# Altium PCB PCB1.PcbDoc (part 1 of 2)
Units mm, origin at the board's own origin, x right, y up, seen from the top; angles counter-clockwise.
Board outline 130 x 90 mm, 2 copper layers (Top Layer, Bottom Layer), stack 1.671 mm thick; 127 components, 100 nets, 530 pads, 140 vias.
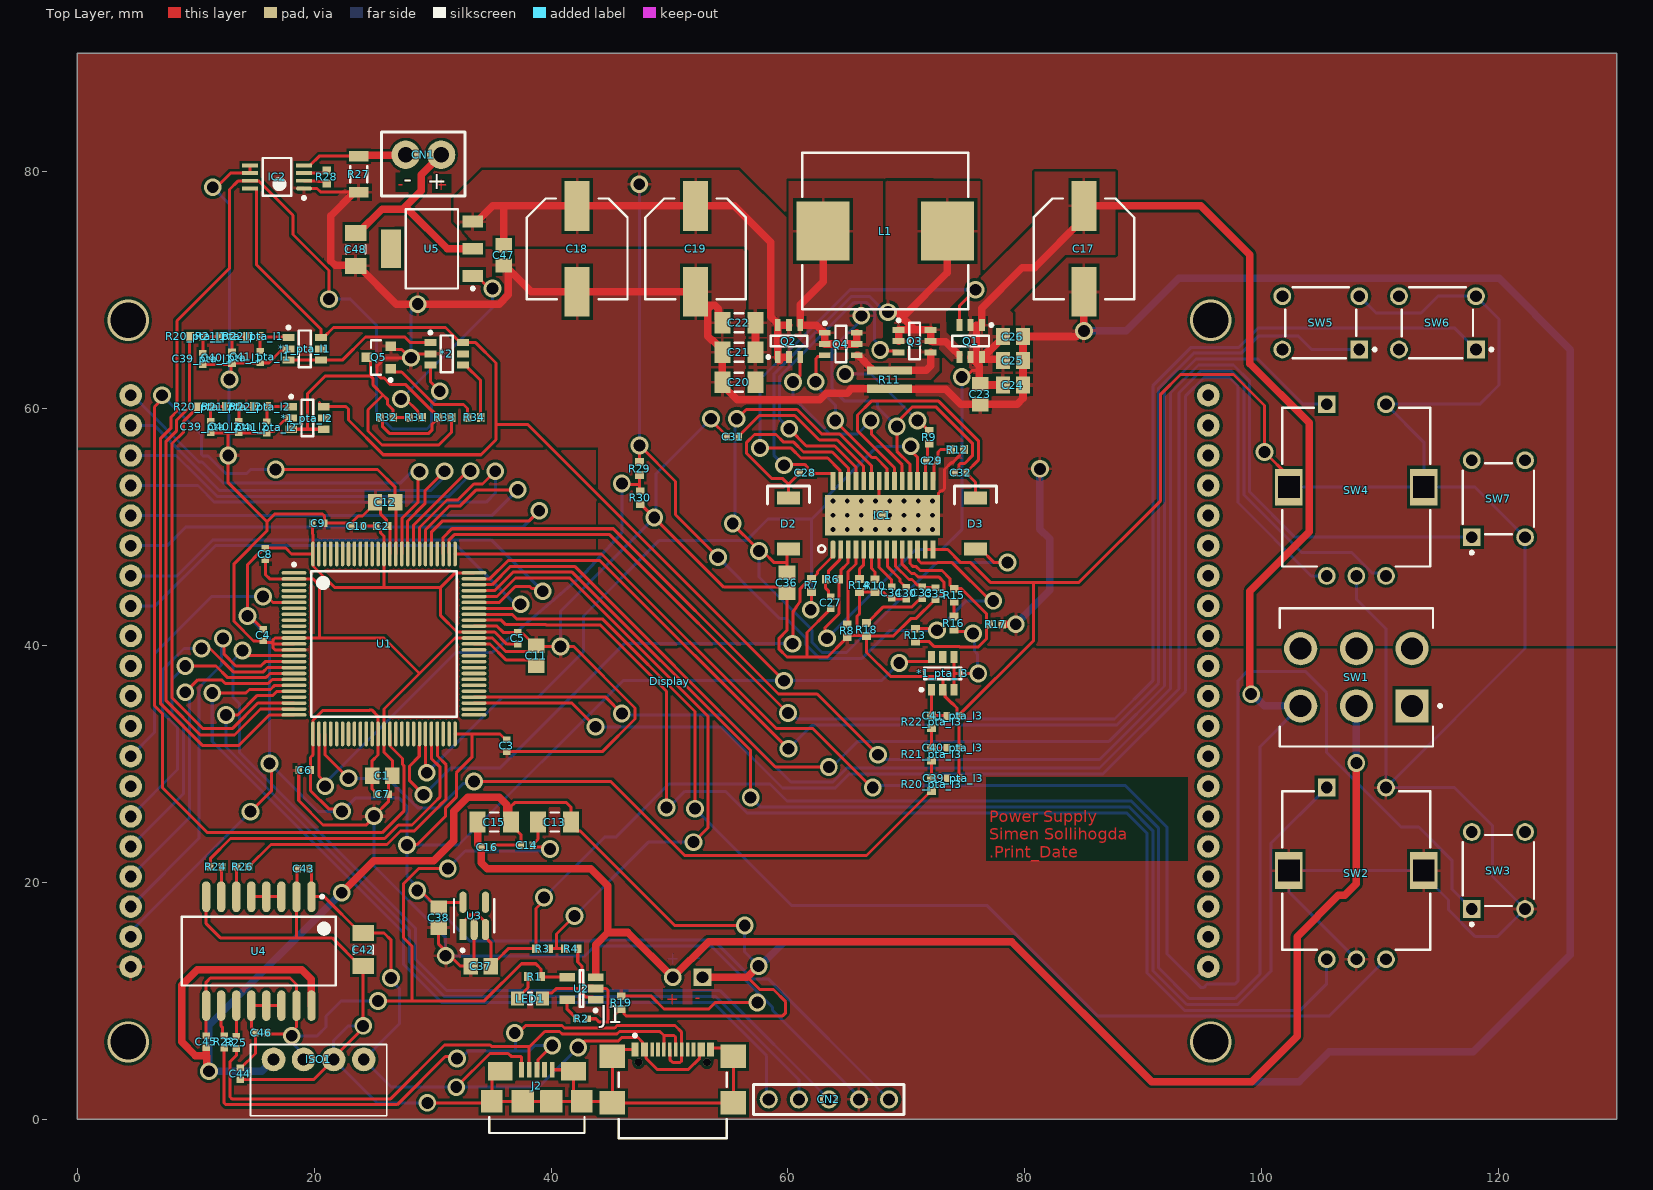
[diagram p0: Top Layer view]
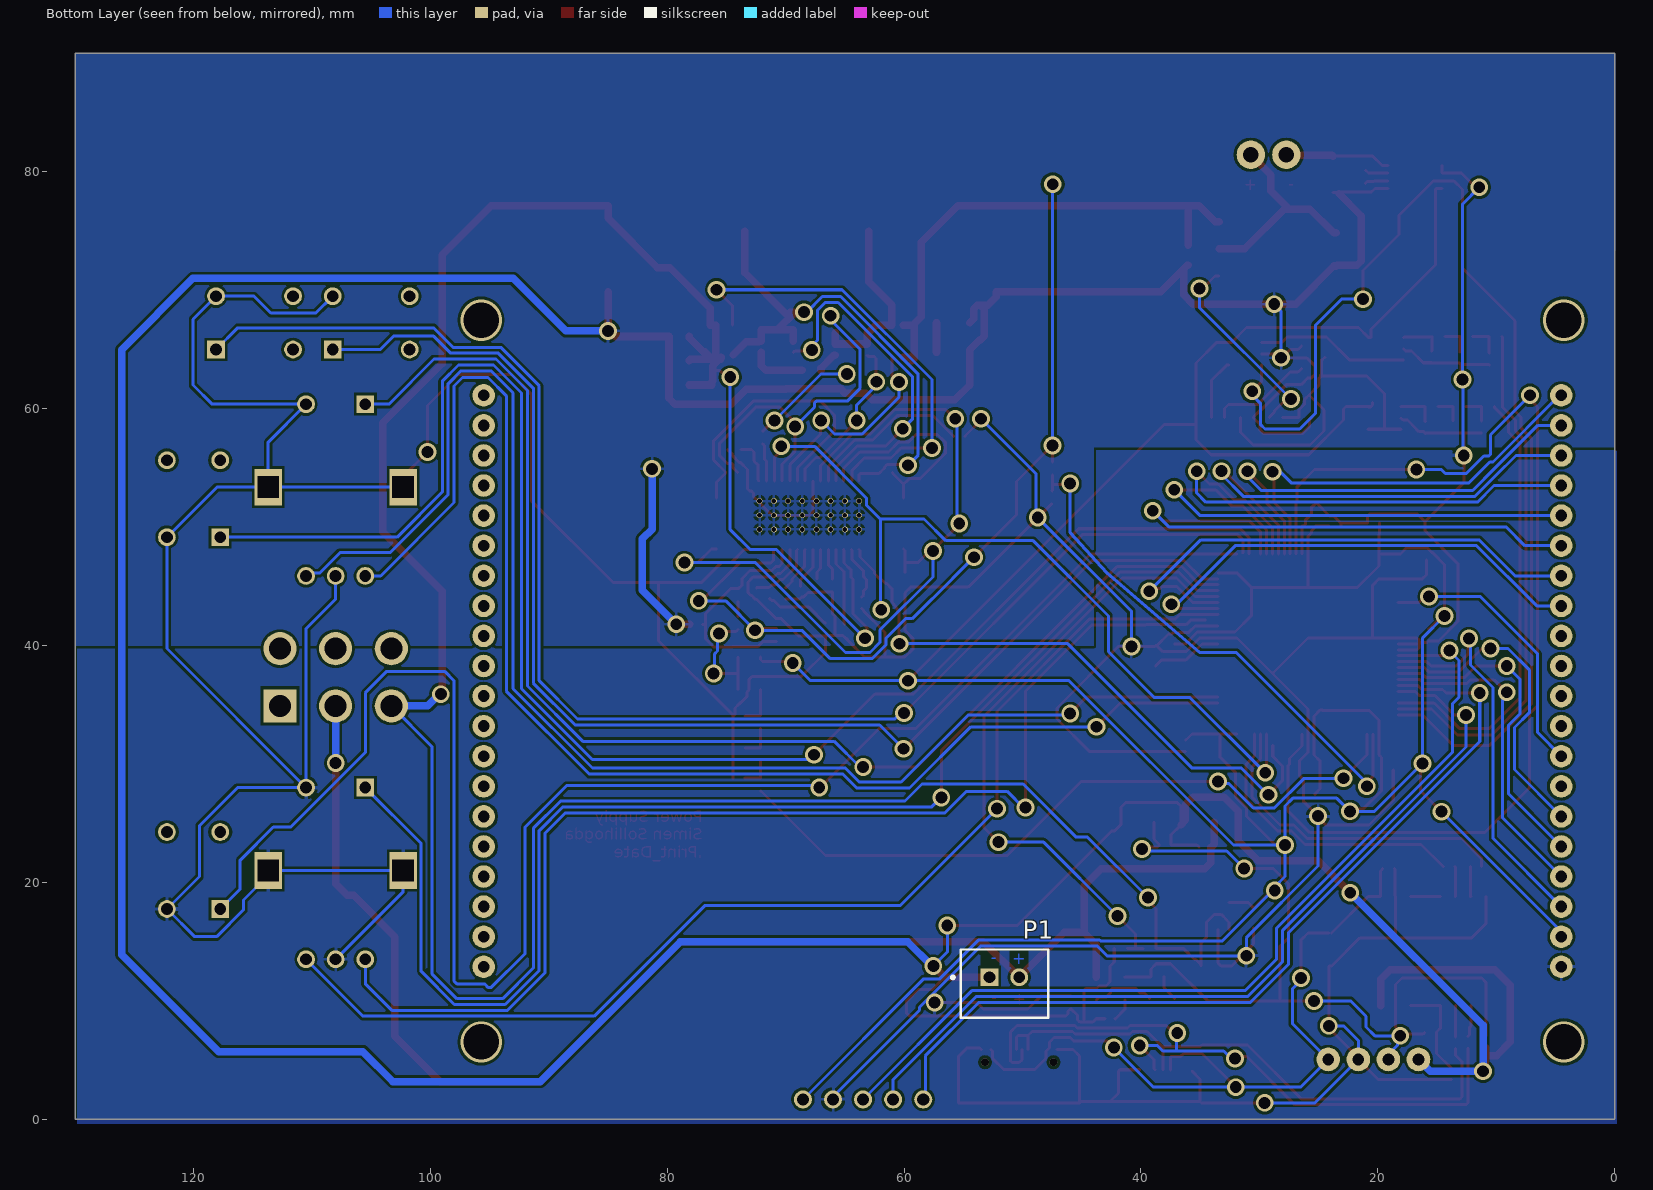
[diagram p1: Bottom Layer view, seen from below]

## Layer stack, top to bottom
Top Solder: solder mask 0.0102, Solder Resist, Dk 3.5
Top Layer: signal copper 0.0356
Dielectric 1: dielectric 1.6, FR-4, Dk 4.8
Bottom Layer: signal copper 0.0356
Bottom Solder: solder mask 0.0102, Solder Resist, Dk 3.5

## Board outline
0,0 130,0 130,90 0,90

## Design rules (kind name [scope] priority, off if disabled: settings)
Clearance Clearance_2 [InComponent('u1') or InComponent('J1') vs IsWire] p1: gap=0.152 ignorepadtopadclearanceinfootprint=FALSE
Clearance Clearance_1 [IsPad vs IsPad] p2: gap=0.152 ignorepadtopadclearanceinfootprint=FALSE
Clearance [All] p3: gap=0.241 ignorepadtopadclearanceinfootprint=FALSE
HoleSize HoleSize_1 [InComponent('IC1') or InComponent('J1')] p1: absolutevalues=TRUE maxlimit=2.54 minlimit=0.3 maxpercent=80.000 minpercent=20.000
HoleSize [All] p2: absolutevalues=TRUE maxlimit=60 minlimit=0.8 maxpercent=80.000 minpercent=20.000
MinimumSolderMaskSliver [All] p1: minsoldermaskwidth=0.102
PolygonConnect [All] p1: connectstyle=Relief reliefconductorwidth=0.254 reliefentries=4 polygonreliefangle="90 Angle" airgapwidth=0.254
RoutingVias [All] p1: holewidth=0.4 width=0.56 viastyle="Through Hole" minholewidth=0.4 minwidth=0.56 maxholewidth=1 maxwidth=2
SilkToSilkClearance [All] p1 off: silktosilkclearance=0.254
SilkToSolderMaskClearance [IsPad] p1: minsilkscreentomaskgap=0 clearancetoexposedcopper=FALSE
SolderMaskExpansion [All] p1: expansion=0.102 istentingtop=FALSE
Width [All] p1: maxlimit=2.54 minlimit=0.203 preferedwidth=0.254
26 further rules are at their usual default settings.

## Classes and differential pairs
component class U_programmer: CN2
component class U_linear_regulator: *2 C47 C48 Q5 R31 R32 R33 R34 U5
component class U_Display: Display
component class pta_I1: *1_pta_I1 C39_pta_I1 C40_pta_I1 C41_pta_I1 R20_pta_I1 R21_pta_I1 R22_pta_I1
component class U_Driver: CN1 R29 R30
component class U_mcu: C1 C2 C3 C4 C5 C6 C7 C8 C9 C10 C11 C12 U1
component class U_knobs: SW2 SW3 SW4 SW5 SW6 SW7
component class U_current_sense: IC2 R27 R28
component class U_Booster: C17 C18 C19 C20 C21 C22 C23 C24 C25 C26 C27 C28 C29 C30 C31 C32 C33 C34 C35 C36 D2 D3 IC1 L1 Q1 Q2 Q3 Q4 R6 R7 R8 R8_U_Booster R9 R10 R11 R12 R13 R14 R15 R16 R17 R18
component class pta_I3: *1_pta_I3 C39_pta_I3 C40_pta_I3 C41_pta_I3 R20_pta_I3 R21_pta_I3 R22_pta_I3
component class pta_I2: *1_pta_I2 C39_pta_I2 C40_pta_I2 C41_pta_I2 R20_pta_I2 R21_pta_I2 R22_pta_I2
component class U_usb_isolator: C42 C43 C44 C45 C46 ISO1 R23 R24 R25 R26 U4
component class U_usb: J1 J2
component class LDO: C37 C38 R19 U3
channel class pwm_to_analog: pta_I3 pta_V
component class Battery: C13 C14 C15 C16 LED1 P1 R1 R2 R3 R4 SW1 U2

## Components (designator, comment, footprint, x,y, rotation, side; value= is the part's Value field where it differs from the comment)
*1_pta_I1 "LMV341IDBVR" SOT95P280X145-6N 19.189,65.05 r0 top (schematic designator *1)
*1_pta_I2 "LMV341IDBVR" SOT95P280X145-6N 19.425,59.214 r0 top (schematic designator *1)
*1_pta_I3 "LMV341IDBVR" SOT95P280X145-6N 73.075,37.641 r90 top (schematic designator *1)
*2 "LMV341IDBVR" SOT95P280X145-6N 31.179,64.625 r0 top
C1 "CL21B105KBFNNNG" CAP0805 25.739,29 r180 top
C2 "GRM155R71H104ME14D" cap0402 25.739,50.092 r180 top value=100nF
C3 "GRM155R71H104ME14D" cap0402 36.243,31.53 r90 top value=100nF
C4 "GRM155R71H104ME14D" cap0402 15.704,40.886 r90 top value=100nF
C5 "GRM155R71H104ME14D" cap0402 37.176,40.617 r270 top value=100nF
C6 "GRM155R71H104ME14D" cap0402 19.189,29.487 r0 top value=100nF
C7 "GRM155R71H104ME14D" cap0402 25.783,27.436 r180 top value=100nF
C8 "GRM155R71H104ME14D" cap0402 15.867,47.728 r90 top value=100nF
C9 "GRM155R71H104ME14D" cap0402 20.349,50.342 r180 top value=100nF
C10 "GRM155R71H104ME14D" cap0402 23.622,50.092 r0 top value=100nF
C11 "CL21B105KBFNNNG" CAP0805 38.752,39.136 r270 top
C12 "CL21B105KBFNNNG" CAP0805 25.986,52.108 r0 top
C13 "CL31A106MBHNNNE" Chip2PinSM127P600-8N#1 40.3,25.095 r180 top
C14 "GRM155R71H104ME14D" cap0402 37.95,23.145 r0 top value=100nF
C15 "CL31A106MBHNNNE" Chip2PinSM127P600-8N#1 35.2,25.095 r180 top
C16 "GRM155R71H104ME14D" cap0402 34.6,22.97 r180 top value=100nF
C17 "EEE-1HA101UP" CAPAE9983X102N 84.999,73.5 r270 top
C18 "EEE-1HA101UP" CAPAE9983X102N 42.199,73.5 r270 top
C19 "EEE-1HA101UP" CAPAE9983X102N 52.199,73.5 r270 top
C20 "CL31A106MBHNNNE" Chip2PinSM127P600-8N#1 55.86,62.225 r0 top
C21 "CL31A106MBHNNNE" Chip2PinSM127P600-8N#1 55.86,64.762 r0 top
C22 "CL31A106MBHNNNE" Chip2PinSM127P600-8N#1 55.86,67.25 r0 top
C23 "CL21B105KBFNNNG" CAP0805 76.25,61.226 r90 top
C24 "CL21B105KBFNNNG" CAP0805 79,62 r180 top
C25 "CL21B105KBFNNNG" CAP0805 79,64.069 r180 top
C26 "CL21B105KBFNNNG" CAP0805 79,66.096 r180 top
C27 "GRM155R71H104ME14D" cap0402 63.6,43.606 r270 top value=100nF
C28 "GRM155R71H104ME14D" cap0402 61.482,54.6 r180 top value=100nF
C29 "885012005078" cap0402 72.163,55.623 r0 top
C30 "GRM155R71H104ME14D" cap0402 69.993,44.42 r90 top value=100nF
C31 "GRM155R71H104ME14D" cap0402 55.345,57.646 r0 top value=100nF
C32 "GRM155R71H104ME14D" cap0402 74.578,54.6 r0 top value=100nF
C33 "CC0402KRX7R9BB223" cap0402 71.343,44.45 r90 top
C34 "885012005080" cap0402 68.763,44.475 r90 top
C35 "885012005080" cap0402 72.463,44.376 r90 top
C36 "CL21B105KBFNNNG" CAP0805 59.917,45.3 r270 top
C37 "CL21B105KBFNNNG" CAP0805 34.055,12.921 r0 top
C38 "CL21B105KBFNNNG" CAP0805 30.5,17.015 r90 top
C39_pta_I1 "GRM155R71H104ME14D" cap0402 10.575,64.2 r90 top value=100nF (schematic designator C39)
C39_pta_I2 "GRM155R71H104ME14D" cap0402 11.249,58.463 r90 top value=100nF (schematic designator C39)
C39_pta_I3 "GRM155R71H104ME14D" cap0402 73.951,28.791 r180 top value=100nF (schematic designator C39)
C40_pta_I1 "GRM155R71H104ME14D" cap0402 13.05,64.3 r90 top value=100nF (schematic designator C40)
C40_pta_I2 "GRM155R71H104ME14D" cap0402 13.625,58.463 r90 top value=100nF (schematic designator C40)
C40_pta_I3 "GRM155R71H104ME14D" cap0402 73.925,31.366 r180 top value=100nF (schematic designator C40)
C41_pta_I1 "GRM155R71H104ME14D" cap0402 15.454,64.375 r90 top value=100nF (schematic designator C41)
C41_pta_I2 "GRM155R71H104ME14D" cap0402 15.979,58.416 r90 top value=100nF (schematic designator C41)
C41_pta_I3 "GRM155R71H104ME14D" cap0402 73.925,34.05 r180 top value=100nF (schematic designator C41)
C42 "CL31A106MBHNNNE" Chip2PinSM127P600-8N#1 24.127,14.321 r90 top
C43 "GRM155R71H104ME14D" cap0402 19.095,21.164 r0 top value=100nF
C44 "GRM155R71H104ME14D" cap0402 13.762,3.833 r270 top value=100nF
C45 "GRM155R71H104ME14D" cap0402 10.872,6.545 r90 top value=100nF
C46 "GRM155R71H104ME14D" cap0402 15.532,7.311 r0 top value=100nF
C47 "CL21B105KBFNNNG" CAP0805 36,72.95 r90 top
C48 "CL31A106MBHNNNE" Chip2PinSM127P600-8N#1 23.495,73.45 r90 top
CN1 "BU-P6883" 6883-Footprint-1 29.213,81.447 r180 top
CN2 "PPTC041LFBN-RC" PR20203VBNN-Footprint-1 63.46,1.665 r90 top locked
D2 "PMEG60T10ELPX" SODFL470X110-2N 60.048,50.3 r270 top
D3 "PMEG60T10ELPX" SODFL470X110-2N 75.841,50.3 r270 top
Display "2050" 2050-Footprint-1 50,37 r90 top locked
IC1 "LM5175-Q1" HTSSOP-28 68,51 r90 top
IC2 "AD8236" 8-MSOP 16.852,79.572 r180 top
ISO1 "RFM-0505S" RFM-0505S-Footprint-1 20.369,5.045 r180 top locked
J1 "USB4110-GF-A" FP-USB4110-GF-A-MFG 50.275,2.204 r0 top locked
J2 "10118192-0001LF" FCI-10118192-0001LF-5_V 38.8,1.5 r0 top locked
L1 "7443551730" INDP130128X65N 68.219,75 r180 top
LED1 "150080BS75000" 0805_A 38.227,10.181 r180 top
P1 "B2B-XH-A(LF)(SN)" JST-B2B-XH-A_V 51.525,11.981 r180 bottom
Q1 "PMN55ENEX" TSOP95P280X110-6N_PMN55ENE 75.425,65.712 r270 top
Q2 "PMN55ENEX" TSOP95P280X110-6N_PMN55ENE 60.087,65.712 r90 top
Q3 "PMN55ENEX" TSOP95P280X110-6N_PMN55ENE 70.697,65.712 r0 top
Q4 "PMN55ENEX" TSOP95P280X110-6N_PMN55ENE 64.465,65.462 r0 top
Q5 "MMBTA42LT1G" ONSC-SOT-23-3-318-08_V 25.445,64.325 r180 top
R1 "RC0402FR-071KL" SMD_0402(1005)_M 38.602,12.035 r0 top value=1k
R2 "RC0402FR-072K2L" RESC1005X40X25NL05T10 42.6,8.481 r180 top value=2.2k
R3 "RC0402FR-0710KL" SMD_0402(1005)_M 39.277,14.396 r180 top value=10k
R4 "RC0402FR-0710KL" SMD_0402(1005)_M 41.7,14.396 r180 top value=10k
R6 "RC0402FR-0710RL" SMD_0402(1005)_M 63.76,45.6 r0 top value=10
R7 "RC0402FR-0710KL" SMD_0402(1005)_M 62,45.075 r90 top value=10k
R8 "RC0402FR-0749K9L" SMD_0402(1005)_M 65.013,41.238 r90 top value=49.9k
R9 "RC0402FR-07100RL" SMD_0402(1005)_M 71.933,57.582 r90 top value=100
R10 "RC0402FR-07100KL" SMD_0402(1005)_M 67.36,45.05 r90 top value=100k
R11 "CFG0612-FX-R010ELF" Chip2PinSM127P600-8N#2 68.597,62.451 r90 top
R12 "RC0402FR-07100RL" SMD_0402(1005)_M 74.316,56.55 r0 top value=100
R13 "RC0402FR-07100k" SMD_0402(1005)_M 70.76,40.871 r90 top value=100k
R14 "RC0402FR-070RL" SMD_0402(1005)_M 66.056,45.075 r90 top value=0
R15 "RC0402FR-0710KL" SMD_0402(1005)_M 74.041,44.25 r270 top value=10k
R16 "RC0402FR-0710KL" SMD_0402(1005)_M 74.016,41.9 r270 top value=10k
R17 "CMP-008-0005-9" SMD_0402(1005)_M 77.55,41.792 r180 top value=10k
R18 "RC0402FR-0710KL" SMD_0402(1005)_M 66.638,41.35 r90 top value=10k
R19 "RC0402FR-070RL" SMD_0402(1005)_M 45.923,9.834 r90 top value=0
R20_pta_I1 "RC0402FR-0710KL" SMD_0402(1005)_M 10.05,66.1 r0 top value=10k (schematic designator R20)
R20_pta_I2 "RC0402FR-0710KL" SMD_0402(1005)_M 10.699,60.164 r0 top value=10k (schematic designator R20)
R20_pta_I3 "RC0402FR-0710KL" SMD_0402(1005)_M 72.125,28.266 r90 top value=10k (schematic designator R20)
R21_pta_I1 "RC0402FR-0710KL" SMD_0402(1005)_M 12.525,66.1 r0 top value=10k (schematic designator R21)
R21_pta_I2 "RC0402FR-0710KL" SMD_0402(1005)_M 13.075,60.177 r0 top value=10k (schematic designator R21)
R21_pta_I3 "RC0402FR-0710KL" SMD_0402(1005)_M 72.125,30.816 r90 top value=10k (schematic designator R21)
R22_pta_I1 "RC0402FR-0710KL" SMD_0402(1005)_M 14.854,66.1 r0 top value=10k (schematic designator R22)
R22_pta_I2 "RC0402FR-0710KL" SMD_0402(1005)_M 15.454,60.177 r0 top value=10k (schematic designator R22)
R22_pta_I3 "RC0402FR-0710KL" SMD_0402(1005)_M 72.125,33.561 r90 top value=10k (schematic designator R22)
R23 "RC0402FR-0724RL" RESC1005X40X25ML05T10 12.389,6.52 r90 top
R24 "RC0402FR-0724RL" RESC1005X40X25ML05T10 11.697,21.33 r180 top
R25 "RC0402FR-0724RL" RESC1005X40X25ML05T10 13.412,6.47 r90 top
R26 "RC0402FR-0724RL" RESC1005X40X25ML05T10 13.962,21.33 r0 top
R27 "ERJ-8BSFR10V" Chip2PinSM127P600-8N#3 23.758,79.797 r270 top value=0.1
R28 "RC0402FR-074K42L" SMD_0402(1005)_M 21.052,79.572 r270 top value=4.42k
R29 "CMP-008-0005-9" SMD_0402(1005)_M 47.474,54.943 r90 top value=10k
R30 "CMP-008-0005-9" SMD_0402(1005)_M 47.524,52.483 r90 top value=10k
R31 "RC0402FR-071KL" SMD_0402(1005)_M 28.575,59.264 r0 top value=1k
R32 "RC0402FR-071KL" SMD_0402(1005)_M 26.114,59.264 r0 top value=1k
R33 "RC0402FR-071KL" SMD_0402(1005)_M 31.036,59.264 r0 top value=1k
R34 "RC0402FR-071KL" SMD_0402(1005)_M 33.497,59.264 r0 top value=1k
SW1 "100DP1T2B3M2QEH" FP-100DP1T2B3M2QEH-MFG 108,37.317 r180 top
SW2 "PEC11R-4215F-S0024" BOUR-PEC11R-4XXXF-SXXXX_V 108,21 r0 top
SW3 "PTS645SM43SMTR92LFS" ITT-PTS645S-4_V 120,21 r90 top
SW4 "PEC11R-4215F-S0024" BOUR-PEC11R-4XXXF-SXXXX_V 108,53.376 r0 top
SW5 "PTS645SM43SMTR92LFS" ITT-PTS645S-4_V 105,67.25 r180 top
SW6 "PTS645SM43SMTR92LFS" ITT-PTS645S-4_V 114.85,67.25 r180 top
SW7 "PTS645SM43SMTR92LFS" ITT-PTS645S-4_V 120,52.394 r90 top
U1 "LMV341IDBVR" CYP-AX100_M 25.889,40.136 r0 top
U2 "MCP73832T-2ACI/OT" SOT-23-OT5_M 42.554,11.031 r180 top
U3 "TLV74333PDBVR" FP-DBV0005A-IPC_A 33.5,17.165 r90 top
U4 "ADUM4160BRIZ-RL" ADI-RI-16-1_M 15.317,14.19 r270 top
U5 "LT3080EST#TRPBF" LT-ST-3-SOT-223_M 29.936,73.5 r180 top

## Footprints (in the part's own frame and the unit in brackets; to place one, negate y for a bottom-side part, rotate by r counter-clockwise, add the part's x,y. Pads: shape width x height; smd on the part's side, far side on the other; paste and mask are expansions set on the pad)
8-MSOP [mm] "TSOP, 8-Leads, Body 3.00x3.00mm, Pitch 0.65mm, IPC Medium Density"
  oval 1.35x0.33 smd: 1(-2.275,0.975)
  rect 1.35x0.33 smd: 2(-2.275,0.325) 3(-2.275,-0.325) 4(-2.275,-0.975) 5(2.275,-0.975) 6(2.275,-0.325) 7(2.275,0.325) 8(2.275,0.975)
  silkscreen extent -2.4,-1.6 1.2,1.9, body extent -2.45,-1.6 2.45,1.6, height 0.95
0805_A [mm] "Chip LED, 2-Leads, Body 2.0x1.3mm, IPC Medium Density"
  rect 1.1x1.2 smd: 1(-1.05,0) 2(1.05,0)
  silkscreen extent -0.15,-0.5 0.15,0.5, body extent -1,-0.62 1,0.63, height 0.68
2050-Footprint-1 [mm]
  round 1.905 hole 1: 1(24.13,-45.5) 2(21.59,-45.5) 3(19.05,-45.5) 4(16.51,-45.5) 5(13.97,-45.5) 6(11.43,-45.5) 7(8.89,-45.5) 8(6.35,-45.5) 9(3.81,-45.5) 10(1.27,-45.5) 11(-1.27,-45.5) 12(-3.81,-45.5) 13(-6.35,-45.5) 14(-8.89,-45.5) 15(-11.43,-45.5) 16(-13.97,-45.5) 17(-16.51,-45.5) 18(-19.05,-45.5) 19(-21.59,-45.5) 20(-24.13,-45.5) 21(-24.13,45.5) 22(-21.59,45.5) 23(-19.05,45.5) 24(-16.51,45.5) 25(-13.97,45.5) 26(-11.43,45.5) 27(-8.89,45.5) 28(-6.35,45.5) 29(-3.81,45.5) 30(-1.27,45.5) 31(1.27,45.5) 32(3.81,45.5) 33(6.35,45.5) 34(8.89,45.5) 35(11.43,45.5) 36(13.97,45.5) 37(16.51,45.5) 38(19.05,45.5) 39(21.59,45.5) 40(24.13,45.5)
  body extent -35,-50 35,50, height 10
6883-Footprint-1 [mm]
  round 2.4 hole 1.3: 1(-1.5,0) 2(1.5,0)
  silkscreen extent -3.5,-1.9 3.53,3.5
ADI-RI-16-1_M [mm] "SOIC, 16-Leads, Body 12.8x7.5mm, Pitch 1.27mm, IPC Low Density"
  oval 2.6x0.7 smd: 1(-4.6,4.445) 2(-4.6,3.175) 3(-4.6,1.905) 4(-4.6,0.635) 5(-4.6,-0.635) 6(-4.6,-1.905) 7(-4.6,-3.175) 8(-4.6,-4.445) 9(4.6,-4.445) 10(4.6,-3.175) 11(4.6,-1.905) 12(4.6,-0.635) 13(4.6,0.635) 14(4.6,1.905) 15(4.6,3.175) 16(4.6,4.445)
  silkscreen extent -4.72,-6.5 2.9,6.5, body extent -3.8,-6.5 3.8,6.5, height 2.65
BOUR-PEC11R-4XXXF-SXXXX_V [mm] "THD, 5-Leads, Body 12.5x13.4mm"
  rect 1.5x1.5 hole 1: 1(-2.5,7)
  round 1.5 hole 1: 2(2.5,7) 3(2.5,-7.5) 4(0,-7.5) 5(-2.5,-7.5)
  rect 2.3x3.1 hole 1.8 square: 6(-5.7,0) 7(5.7,0)
  silkscreen extent -6.25,-6.7 6.25,6.7, body extent -7,-7.7 7,7.2, height 21.61
cap0402 [mm] "0402 footprint for capasitors"
  rect 0.54x0.64 smd: 1(-0.5,0) 2(0.5,0)
  body extent -0.5,-0.25 0.5,0.25, height 0.5
CAP0805 [mm] "0804 smd capasitor"
  rect 1.2x1.4 smd: 1(-0.85,0) 2(0.85,0)
  body extent -1.05,-0.63 1.05,0.63, height 1.35
CAPAE9983X102N [mm] "Aluminum Electrolytic Capacitor, Body 8.30x8.30x10.20mm, IPC Medium Density"
  rect 4.2x2.1 smd: 1(-3.625,0) 2(3.625,0)
  silkscreen extent -4.25,-4.25 4.25,4.25, body extent -4.95,-4.25 4.95,4.25, height 10.2
Chip2PinSM127P600-8N#1 [mm] "1206 ceramic capasitor"
  rect 1.35x1.8 smd: 1(-1.4,0) 2(1.4,0)
  silkscreen extent -0.35,-0.8 0.35,0.8, body extent -1.7,-0.87 1.7,0.87, height 1.6
Chip2PinSM127P600-8N#2 [mm] "1206 flipped sens resitor"
  rect 0.7x3.8 smd: 1(-0.775,0) 2(0.775,0)
  body extent -0.8,-1.7 0.8,1.7, height 0.7
Chip2PinSM127P600-8N#3 [mm]
  rect 0.9x1.65 smd: 1(-1.525,0) 2(1.525,0)
  silkscreen extent -0.7,-0.73 0.7,0.73, body extent -1.6,-0.8 1.6,0.8, height 0.5
CYP-AX100_M [mm] "QFN, 100-Leads, Body 14x14mm, Pitch 0.5mm, IPC Low Density"
  oval 2.1x0.3 smd: 1(-7.6,6) 2(-7.6,5.5) 3(-7.6,5) 4(-7.6,4.5) 5(-7.6,4) 6(-7.6,3.5) 7(-7.6,3) 8(-7.6,2.5) 9(-7.6,2) 10(-7.6,1.5) 11(-7.6,1) 12(-7.6,0.5) 13(-7.6,0) 14(-7.6,-0.5) 15(-7.6,-1) 16(-7.6,-1.5) 17(-7.6,-2) 18(-7.6,-2.5) 19(-7.6,-3) 20(-7.6,-3.5) 21(-7.6,-4) 22(-7.6,-4.5) 23(-7.6,-5) 24(-7.6,-5.5) 25(-7.6,-6) 51(7.6,-6) 52(7.6,-5.5) 53(7.6,-5) 54(7.6,-4.5) 55(7.6,-4) 56(7.6,-3.5) 57(7.6,-3) 58(7.6,-2.5) 59(7.6,-2) 60(7.6,-1.5) 61(7.6,-1) 62(7.6,-0.5) 63(7.6,0) 64(7.6,0.5) 65(7.6,1) 66(7.6,1.5) 67(7.6,2) 68(7.6,2.5) 69(7.6,3) 70(7.6,3.5) 71(7.6,4) 72(7.6,4.5) 73(7.6,5) 74(7.6,5.5) 75(7.6,6)
  oval 0.3x2.1 smd: 26(-6,-7.6) 27(-5.5,-7.6) 28(-5,-7.6) 29(-4.5,-7.6) 30(-4,-7.6) 31(-3.5,-7.6) 32(-3,-7.6) 33(-2.5,-7.6) 34(-2,-7.6) 35(-1.5,-7.6) 36(-1,-7.6) 37(-0.5,-7.6) 38(0,-7.6) 39(0.5,-7.6) 40(1,-7.6) 41(1.5,-7.6) 42(2,-7.6) 43(2.5,-7.6) 44(3,-7.6) 45(3.5,-7.6) 46(4,-7.6) 47(4.5,-7.6) 48(5,-7.6) 49(5.5,-7.6) 50(6,-7.6) 76(6,7.6) 77(5.5,7.6) 78(5,7.6) 79(4.5,7.6) 80(4,7.6) 81(3.5,7.6) 82(3,7.6) 83(2.5,7.6) 84(2,7.6) 85(1.5,7.6) 86(1,7.6) 87(0.5,7.6) 88(0,7.6) 89(-0.5,7.6) 90(-1,7.6) 91(-1.5,7.6) 92(-2,7.6) 93(-2.5,7.6) 94(-3,7.6) 95(-3.5,7.6) 96(-4,7.6) 97(-4.5,7.6) 98(-5,7.6) 99(-5.5,7.6) 100(-6,7.6)
  silkscreen extent -7.72,-6.15 6.15,6.82, body extent -7,-7 7,7, height 1.6
FCI-10118192-0001LF-5_V [mm] "SMD, 5-Leads, Body 8.05x5.77mm, Pitch 0.65mm"
  rect 0.4x1.35 smd mask+0.05: 1(-1.3,2.675) 2(-0.65,2.675) 3(0,2.675) 4(0.65,2.675) 5(1.3,2.675)
  rect 2.1x1.6 smd: 6(-3.1,2.55) 7(3.1,2.55)
  rect 1.8x1.9 smd: 8(-3.8,0) 9(3.8,0)
  rect 1.9x1.9 smd: 10(-1.2,0) 11(1.2,0)
  silkscreen extent -4.03,-2.67 4.03,-1.35, body extent -4.03,-2.67 4.03,3.1, height 2.7
FP-100DP1T2B3M2QEH-MFG [mm]
  rect 2.8x2.8 hole 1.85 paste-1000 mask+0: 1(-4.7,2.415)
  round 2.8 hole 1.85 paste-1000 mask+0: 2(0,2.415) 3(4.7,2.415) 4(-4.7,-2.415) 5(0,-2.415) 6(4.7,-2.415)
  silkscreen extent -7.2,-5.84 6.48,5.84, body extent -6.58,-5.94 6.58,5.94, height 0.25
FP-DBV0005A-IPC_A [mm]
  rect 1.805x0.612 smd paste+0 mask+0: 1(-1.15,0.95)
  rrect100% 1.805x0.612 smd paste+0 mask+0: 2(-1.15,0) 3(-1.15,-0.95) 4(1.151,-0.95) 5(1.151,0.95)
  silkscreen extent -3.03,-1.7 1.4,1.7, body extent -2.55,-1.95 2.55,1.95, height 0.25
FP-USB4110-GF-A-MFG [mm]
  rect 2.18x2 smd paste+0 mask+0: 1(-5.11,3.105) 2(5.11,3.105) 3(-5.11,-0.825) 4(5.11,-0.825)
  rect 0.6x1.15 smd paste+0 mask+0: A1-B12(-3.2,3.68) A4-B9(-2.4,3.68) B1-A12(3.2,3.68) B4-A9(2.4,3.68)
  rect 0.3x1.15 smd paste+0 mask+0: A5(-1.25,3.68) A6(-0.25,3.68) A7(0.25,3.68) A8(1.25,3.68) B5(1.75,3.68) B6(0.75,3.68) B7(-0.75,3.68) B8(-1.75,3.68)
  round 0.65 hole 0.65 unplated paste-1000 mask+0: ""(-2.89,2.605) ""(2.89,2.605)
  silkscreen extent -4.57,-3.83 4.57,4.99, body extent -6.3,-3.92 6.3,4.36, height 0.25
HTSSOP-28 [mm]
  rrect50% 1.5x0.4 smd mask+0.05: 1(-2.9,4.2)
  rect 1.5x0.4 smd mask+0.05: 2(-2.9,3.55) 3(-2.9,2.9) 4(-2.9,2.25) 5(-2.9,1.6) 6(-2.9,0.95) 7(-2.9,0.3) 8(-2.9,-0.35) 9(-2.9,-1) 10(-2.9,-1.65) 11(-2.9,-2.3) 12(-2.9,-2.95) 13(-2.9,-3.6) 14(-2.9,-4.25) 15(2.9,-4.25) 16(2.9,-3.6) 17(2.9,-2.95) 18(2.9,-2.3) 19(2.9,-1.65) 20(2.9,-1) 21(2.9,-0.35) 22(2.9,0.3) 23(2.9,0.95) 24(2.9,1.6) 25(2.9,2.25) 26(2.9,2.9) 27(2.9,3.55) 28(2.9,4.2)
  rect 3.4x9.7 smd paste-100 mask+0.102: -(0,0)
  silkscreen extent -3.14,4.86 -2.55,5.46, body extent -3.2,-4.9 3.2,7.24, height 0.97
INDP130128X65N [mm] "Precision Wire Wound Inductor, 2-Leads, Body 13.00x12.75mm, IPC Medium Density"
  rect 4.5x5 smd: 1(-5.25,0) 2(5.25,0)
  silkscreen extent -7,-6.6 7,6.6, body extent -6.6,-6.38 6.6,6.38, height 6.6
ITT-PTS645S-4_V [mm] "TH, 4-Leads, Body 6x6mm"
  rect 1.5x1.5 hole 1: 1(-3.25,2.25)
  round 1.5 hole 1: 2(3.25,2.25) 3(-3.25,-2.25) 4(3.25,-2.25)
  silkscreen extent -4.67,-3 3,3, body extent -3,-3 3,3, height 4.4
JST-B2B-XH-A_V [mm] "Header, 2-Leads, Body 7.4x5.75mm, Pitch 2.5mm"
  rect 1.5x1.5 hole 1: 1(-1.25,0)
  round 1.5 hole 1: 2(1.25,0)
  silkscreen extent -4.47,-3.4 3.7,2.35, body extent -3.7,-3.4 3.7,2.35, height 7
LT-ST-3-SOT-223_M [mm] "SOT223, 4-Leads, Body 6.505x3.505mm, Pitch 2.3mm, IPC Low Density"
  rect 1.7x1 smd: 1(-3.45,2.3) 2(-3.45,0) 3(-3.45,-2.3)
  rect 1.7x3.25 smd: 4(3.45,0)
  silkscreen extent -3.58,-3.35 2.2,3.47, body extent -1.86,-3.35 1.86,3.35, height 1.8
ONSC-SOT-23-3-318-08_V [mm] "SOT23, 3-Leads, Body 2.92x1.3mm, Pitch 0.95mm"
  rect 0.9x0.8 smd: 1(-1,0.95) 2(-1,-0.95) 3(1,0)
  silkscreen extent -1.13,-1.46 0.65,2.02, body extent -0.65,-1.46 0.65,1.46, height 1.11
PR20203VBNN-Footprint-1 [mil]
  round 60 hole 40: 1(0,200) 2(0,100) 3(0,0)
  round 60 hole 39.37: 4(0,-100) 5(0,-200)
  silkscreen extent -50,-250 50,250, body extent -50,-260 300,260, height 335
RESC1005X40X25ML05T10 [mm] "Chip Resistor, 2-Leads, Body 1.00x0.50mm, IPC Low Density"
  rect 0.6x0.65 smd: 1(-0.508,0) 2(0.508,0)
  body extent -0.53,-0.27 0.53,0.28, height 0.4
RESC1005X40X25NL05T10 [mm] "Chip Resistor, 2-Leads, Body 1.00x0.50mm, IPC Medium Density"
  rect 0.5x0.55 smd: 1(-0.508,0) 2(0.508,0)
  body extent -0.53,-0.27 0.53,0.28, height 0.4
RFM-0505S-Footprint-1 [mm]
  round 2 hole 1: 1(-3.81,0) 2(-1.27,0) 3(1.27,0) 4(3.81,0)
  silkscreen extent -5.75,-1.25 5.75,4.75, body extent -5.8,-1.25 5.7,4.75, height 9.5
SMD_0402(1005)_M [mm] "Chip Resistor, Body 1.0x0.5mm, IPC Low Density"
  rect 0.65x0.75 smd: 1(-0.55,0) 2(0.55,0)
  body extent -0.52,-0.28 0.53,0.28, height 0.4
SODFL470X110-2N [mm] "SODFL, 2-Leads, Body 2.50x4.70mm, IPC Medium Density"
  rect 1.1x1.95 smd: 1(-2.15,0) 2(2.15,0)
  silkscreen extent -3.18,-1.78 -1.65,1.78, body extent -2.35,-1.35 2.35,1.35, height 1.1
SOT95P280X145-6N [mm] "SOT23, 6-Leads, Body 2.90x2.80mm, Pitch 0.95mm, IPC Medium Density"
  rect 1x0.6 smd: 1(-1.375,0.95) 2(-1.375,0) 3(-1.375,-0.95) 4(1.375,-0.95) 5(1.375,0) 6(1.375,0.95)
  silkscreen extent -1.5,-1.55 0.5,1.92, body extent -1.5,-1.53 1.5,1.53, height 1.45
SOT-23-OT5_M [mm] "SOT23, 5-Leads, Body 2.9x1.7mm, Pitch 0.95mm, Lead Span 2.8mm, IPC Low Density"
  rect 1.3x0.65 smd mask+0.05: 1(-1.2,0.95) 2(-1.2,0) 3(-1.2,-0.95)
  rect 1.3x0.7 smd: 4(1.2,-0.95) 5(1.2,0.95)
  silkscreen extent -1.33,-1.55 0.15,1.97, body extent -0.9,-1.55 0.9,1.55, height 1.45
TSOP95P280X110-6N_PMN55ENE [mm] "pin maping matches PMN55ENE- TSOP, 6-Leads, Body 2.90x1.50mm, Pitch 0.95mm, IPC Medium Density"
  rect 1x0.5 smd: 1(1.35,-0.95) 2(-1.35,0.95) 2(-1.35,0) 2(1.35,0.95) 2(1.35,0) 3(-1.35,-0.95)
  silkscreen extent -1.47,-1.55 0.45,1.88, body extent -1.38,-1.55 1.38,1.55, height 1.1

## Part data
*1_pta_I1 *1_pta_I2 *1_pta_I3 *2: library part CMP-ROOT-00000-1, "Single Rail-To-Rail Output CMOS Operational Amplifier with Shutdown 6-SOT-23 -40 to 125", Case/Package=SOT-23, Input Bias Current=200pA, Input Offset Voltage (Vos)=250uV, Max Frequency=1kHz, Max Operating Temperature=125°C, Max Supply Voltage=5.5V, Min Operating Temperature=-40°C, Min Supply Voltage=2.5V, Nominal Supply Current=170uA, Operating Supply Current=107uA, Output Current=32mA, Output Current per Channel=113mA, Package Quantity=1, Voltage Gain=116dB
C1 C11 C12 C23 C24 C25 C26 C36 C37 C38 C47: library part CMP-0001-00012-4, "SAMSUNG ELECTRO-MECHANICS - CL21B105KBFNNNG - MLCC CAPACITORS", Capacitance=1µF, Capacitor Type=Ceramic, Case Code (Imperial)=0805, Case Code (Metric)=2012, Dielectric=X7R, Max Operating Temperature=125°C, Min Operating Temperature=-55°C, Package Quantity=3000, Tolerance=10%, Voltage=50V
C2 C3 C4 C5 C6 C7 C8 C9 C10 C14 C16 C27 C28 C30 C31 C32 C39_pta_I1 C39_pta_I2 C39_pta_I3 C40_pta_I1 C40_pta_I2 C40_pta_I3 C41_pta_I1 C41_pta_I2 C41_pta_I3 C43 C44 C45 C46: library part CMP-0001-00001-8, "0402 0.1 uF 50 V ±20% Tolerance X7R SMT Monolithic Ceramic Chip Capacitor", Capacitance=100nF, Capacitor Type=Ceramic, Case/Package=0402, Max Operating Temperature=125°C, Min Operating Temperature=-55°C, Tolerance=20%, Voltage Rating=50V
C13 C15 C20 C21 C22 C42 C48: library part CMP-0001-00015-2, "CAP CER 10UF 50V X5R 1206", Capacitance=10µF, Capacitor Type=Ceramic, Case Code (Imperial)=1206, Case Code (Metric)=3216, Dielectric=X5R, Max Operating Temperature=85°C, Min Operating Temperature=-55°C, Tolerance=20%, Voltage Rating=50V
C17 C18 C19: library part CMP-0001-00014-2, "Cap Aluminum 100uF 50V 20% (8 X 10.2mm) SMD 200mA 2000 hr 85C T/R", Capacitance=100µF, Capacitor Type=Ceramic, Case/Package=Radial, Max Operating Temperature=85°C, Min Operating Temperature=-40°C, Package Quantity=1, Ripple Current=200mA, Tolerance=20%, Voltage Rating=50V
C29: library part CMP-0001-00009-6, "CAP CER 47PF 100V C0G/NP0 0402", Capacitance=47pF, Capacitor Type=Ceramic, Case Code (Imperial)=0402, Case Code (Metric)=1005, Max Operating Temperature=125°C, Min Operating Temperature=-55°C, Tolerance=5%, Voltage Rating=100V
C33: library part CMP-0001-00011-3, "Multilayer Ceramic Capacitors MLCC - SMD/SMT 22K pF 10% 50 Volts", Capacitance=22nF, Capacitor Type=Ceramic, Case Code (Imperial)=0402, Case Code (Metric)=1005, Dielectric=X7R, Max Operating Temperature=125°C, Min Operating Temperature=-55°C, Package Quantity=10000, Tolerance=10%, Voltage Rating=50V
C34 C35: library part CMP-0001-00010-3, "Cap, Mlcc, C0g, 100Pf, 100V, 0402", Capacitance=100pF, Capacitor Type=Ceramic, Case Code (Imperial)=0402, Case Code (Metric)=1005, Max Operating Temperature=125°C, Min Operating Temperature=-55°C, Tolerance=5%, Voltage Rating=100V
CN1: library part CMP-ROOT-00006-6, "CONN BIND POST DL FLUTD BLK/RED", Color=Black,Red
CN2: library part CMP-ROOT-00017-7, "CONN HDR 5POS 0.1 GOLD PCB used for connecting to cypress kitprog_usb", Color=Black, Package Quantity=1000
D2 D3: library part CMP-ROOT-00002-1, "Diode Schottky 60V 1A Surface Mount CFP5", Case/Package=SMA, Operating Temperature - Junction="175°C (Max)", Package / Case=SOD-128, Voltage - Forward (Vf) (Max) @ If="590mV @ 1A"
Display: library part CMP-ROOT-00015-3, "3.5\" TFT 320X480 TOUCHSCREEN", Case/Package=pcb
IC1: library part CMP-006-0002-14, "IC REG CTRLR BUCK-BOOST 28HTSSOP", Max Operating Temperature=125°C, Max Supply Voltage=42V, Min Operating Temperature=-40°C, Min Supply Voltage=3.5V, Quiescent Current=1.65mA, Switching Frequency=600kHz
IC2: library part CMP-006-0000-5, "IC OPAMP INSTR 23KHZ RRO 8MSOP", Case/Package=MSOP, Input Bias Current=10pA, Input Offset Voltage (Vos)=3.5mV, Input Resistance=440GR, Max Operating Temperature=125°C, Max Supply Voltage=5.5V, Min Operating Temperature=-40°C, Min Supply Voltage=1.8V, Operating Supply Current=40uA, Output Current per Channel=6mA, Package Quantity=1, Power Supply Rejection Ratio (PSRR)=130dB, Voltage Gain=46.02dB
ISO1: library part CMP-ROOT-00011-2, "RECOM POWER - RFM-0505S - Isolated Board Mount DC/DC Converter, ITE & General, 1 Output, 1 W, 5 V, 200 mA", Case/Package=dip, Max Output Voltage=5V
J1: library part CMP-ROOT-00018-1, "Conn Usb 2.0 Type-c R/a SMT"
J2: library part CMP-ROOT-00010-2, "CONN RCPT USB2.0 MICRO B SMD R/A", Color=Black, Current Rating=1.8A, Flammability Rating="UL94 V-0", Insulation Resistance=1GR, Max Operating Temperature=85°C, Max Voltage Rating (AC)=100V, Min Operating Temperature=-55°C, Package Quantity=1400
L1: library part CMP-ROOT-00003-1, "WURTH ELEKTRONIK         7443551730             Surface Mount Power Inductor, WE-HCI Series, 7.3 H, 13 A, 12 A, Shielded, 5900 ohm", Case/Package=1365, Current Rating=13A, DC Resistance (DCR)=5.9mR, Inductance=7.3uH, Inductance Tolerance=20%, Max Operating Temperature=155°C, Min Operating Temperature=-40°C, Package Quantity=400, Saturation Current=12A, Self Resonant Frequency=28MHz, Series Resistance=5.9R, Test Frequency=100kHz
LED1: library part CMP-00002-1, "SMD LED blue 3.5 V 0805, 150080BS75000, Würth Elektronik", Case Code (Imperial)=0805, Case Code (Metric)=2012, Color=Blue, Forward Current=30mA, Forward Voltage=3.2V, Max Operating Temperature=85°C, Min Operating Temperature=-40°C, Package Quantity=4000, Test Current=20mA
P1: library part CMP-ROOT-00008-1, "Conn Shrouded Header (4 Sides) HDR 2 POS 2.5mm Solder ST Thru-Hole Box", Color=Natural, Contact Resistance=20mR, Current Rating=3A, Housing Color=White, Insulation Resistance=1GR, Max Operating Temperature=85°C, Max Voltage Rating (AC)=250V, Min Operating Temperature=-25°C
Q1 Q2 Q3 Q4: library part CMP-ROOT-00001-4, "MOSFET N-CH 60V 4.5A 6TSOP", Case/Package=TSOP, Continuous Drain Current (ID)=4.5A, Drain to Source Voltage (Vdss)=60V, Input Capacitance=646pF, Max Operating Temperature=150°C, Max Power Dissipation=6.25mW, Min Operating Temperature=-55°C
Q5: library part CMP-ROOT-00016-1, "Trans GP BJT NPN 300V 0.5A Automotive 3-Pin SOT-23 T/R", Case/Package=SOT-23-3, Collector Base Voltage (VCBO)=300V, Collector Emitter Saturation Voltage=500mV, Current Rating=500mA, Emitter Base Voltage (VEBO)=6V, Frequency=50MHz, Max Operating Temperature=150°C, Max Power Dissipation=225mW, Min Operating Temperature=-55°C, Package Quantity=1, Power Dissipation=300mW
R1 R31 R32 R33 R34: library part CMP-001-0000-7, "Surface Mount Chip Resistor, Thick Film, RC Series, 1 kohm, 62.5 mW, 1%, 50 V, 0402 [1005 Metric]", Case Code (Imperial)=0402, Case Code (Metric)=1005, Max Operating Temperature=155°C, Min Operating Temperature=-55°C, Power Rating=62.5mW, Resistance=1k, Temperature Coefficient=100ppm/°C, Tolerance=1%, Voltage Rating=50V
R2: library part CMP-001-0020-3, "RES SMD 2.2K OHM 1% 1/16W 0402", Case Code (Imperial)=0402, Case Code (Metric)=1005, Max Operating Temperature=155°C, Min Operating Temperature=-55°C, Power Rating=63mW, Resistance=2.2k, Temperature Coefficient=100ppm/°C, Tolerance=1%, Voltage Rating=50V
R3 R4 R7 R15 R16 R18 R20_pta_I1 R20_pta_I2 R20_pta_I3 R21_pta_I1 R21_pta_I2 R21_pta_I3 R22_pta_I1 R22_pta_I2 R22_pta_I3: library part CMP-008-0005-9, "Surface Mount Thick Film Resistor, Rc Series, 10 Kohm, 62.5 Mw, - 1%, 50 V, 0402 [1005 Metric]", Case Code (Imperial)=0402, Case Code (Metric)=1005, Max Operating Temperature=155°C, Min Operating Temperature=-55°C, Power Rating=62.5mW, Resistance=10k, Temperature Coefficient=100ppm/°C, Tolerance=1%, Voltage Rating=50V
R6: library part CMP-0001-00007-3, "RES SMD 10 OHM 1% 1/16W 0402", Case Code (Imperial)=0402, Case Code (Metric)=1005, Max Operating Temperature=155°C, Min Operating Temperature=-55°C, Power Rating=63mW, Resistance=10, Temperature Coefficient=100ppm/°C, Tolerance=1%, Voltage Rating=50V
R8: library part CMP-0001-00013-2, "Res Thick Film 0402 49.9K Ohm 1% 0.063W(1/16W) ±100ppm/C Epoxy Pad SMD T/R", Case Code (Imperial)=0402, Case Code (Metric)=1005, Max Operating Temperature=155°C, Min Operating Temperature=-55°C, Power Rating=62.5mW, Resistance=49.9k, Temperature Coefficient=100ppm/°C, Tolerance=1%, Voltage Rating=50V
R9 R12: library part CMP-0001-00008-3, "YAGEO - RC0402FR-07100RL. - RES, THICK FILM, 100R, 1%, 0.0625W, 0402, REEL", Case Code (Imperial)=0402, Case Code (Metric)=1005, Max Operating Temperature=155°C, Min Operating Temperature=-55°C, Power Rating=62.5mW, Resistance=100, Temperature Coefficient=100ppm/°C, Tolerance=1%, Voltage Rating=50V
R10 R13: library part CMP-0001-00006-4, "Res General Purpose Thick Film 0402 100K Ohm 1% 1/16W ±100ppm/°C Molded SMD Paper T/R", Case Code (Imperial)=0402, Case Code (Metric)=1005, Max Operating Temperature=155°C, Max Power Dissipation=63mW, Min Operating Temperature=-55°C, Package Quantity=1, Resistance=100k, Temperature Coefficient=100ppm/°C, Tolerance=1%, Voltage Rating=50V
R11: library part CMP-0001-00016-1, "BOURNS JW MILLER - CFG0612-FX-R010ELF - SMD Current Sense Resistor, 0.01 ohm, CFG Series, 1206 Wide, 1 W, ± 1%, Metal Foil", Case/Package="Wide 1206 (3216 Metric), 0612", Resistance=10m
R14 R19: library part CMP-0001-00005-6, "Res Thick Film 0402 0 Ohm Molded SMD SMD Paper T/R", Case Code (Imperial)=0402, Case Code (Metric)=1005, Max Operating Temperature=155°C, Min Operating Temperature=-55°C, Power Rating=62.5mW, Resistance=0, Temperature Coefficient=200ppm/°C, Tolerance=1%, Voltage Rating=50V
R17 R29 R30: "Surface Mount Thick Film Resistor, Rc Series, 10 Kohm, 62.5 Mw, - 1%, 50 V, 0402 [1005 Metric]", Case Code (Imperial)=0402, Case Code (Metric)=1005, Max Operating Temperature=155°C, Min Operating Temperature=-55°C, Power Rating=62.5mW, Resistance=10k, Temperature Coefficient=100ppm/°C, Tolerance=1%, Voltage Rating=50V
R23 R24 R25 R26: library part CMP-0001-00017-2, "Thick Film Resistors 24 OHM 1%", Case Code (Imperial)=0402, Case Code (Metric)=1005, Max Operating Temperature=155°C, Max Power Dissipation=63mW, Min Operating Temperature=-55°C, Resistance=24, Temperature Coefficient=100ppm/°C, Tolerance=1%, Voltage Rating=50V
R27: library part CMP-0001-00003-2, "Precision resistor, SMD 0.1 Ohm 0.33 W  ±  1 % 1206, ERJ8BSFR10V, Panasonic Automotive & Industrial Systems", Case Code (Imperial)=1206, Case Code (Metric)=3216, Max Operating Temperature=125°C, Max Power Dissipation=500mW, Min Operating Temperature=-55°C, Package Quantity=5000, Power Rating=330mW, Resistance=0.1, Temperature Coefficient=250ppm/°C, Tolerance=1%
R28: library part CMP-0001-00002-5, "RES SMD 4.42K OHM 1% 1/16W 0402", Case Code (Imperial)=0402, Case Code (Metric)=1005, Max Operating Temperature=155°C, Max Power Dissipation=63mW, Min Operating Temperature=-55°C, Power Rating=62.5mW, Resistance=4.42k, Temperature Coefficient=100ppm/°C, Tolerance=1%, Voltage Rating=50V
SW1: library part CMP-ROOT-00014-1, "100 Series DPDT On-None-On Through Hole Miniature Toggle Switch", Case/Package=dip, Current Rating=5A, Max Operating Temperature=85°C, Min Operating Temperature=-30°C, Package Quantity=200, Voltage Rating (AC)=120V, Voltage Rating (DC)=28V
SW2 SW4: library part CMP-ROOT-00012-1, "BOURNS - PEC11R-4215F-S0024 - Rotary Encoder, Mechanical, Incremental, 24 PPR, 24 Detents, Vertical, With Momentary Push Switch", Case/Package=encoder, Max Operating Temperature=70°C, Min Operating Temperature=-30°C, Package Quantity=150
SW3 SW5 SW6 SW7: library part CMP-ROOT-00013-1, "SWITCH TACTILE SPST-NO 0.05A 12V", Case/Package=SMD/SMT, Color=Black, Contact Resistance=100mR, Current Rating=50mA, Max Operating Temperature=60°C, Max Voltage Rating (DC)=12V, Min Operating Temperature=-20°C, Operating Force=160gf, Package Quantity=1
U1: library part CMP-00001-1, "IC MCU 32BIT 128KB FLASH 100TQFP", Case/Package=TQFP, Frequency=67MHz, Max Operating Temperature=85°C, Max Supply Voltage=5.5V, Min Operating Temperature=-40°C, Min Supply Voltage=1.71V, Package Quantity=1
U2: library part CMP-006-0003-2, "BATTERY CHARGER, 500mA, SOT23-5; Battery Type:Li-Ion, Li-Pol; Input Voltage:6V; Battery Charge Voltage:4.2V; Charge Current Max:500mA; Battery IC Case Style:SOT-23; No. of Pins:5; No. of Series Cells:1; Operating Temperature Max:85 C", Case/Package=SOT-23, Max Charge Current=500mA, Max Input Voltage=6V, Max Operating Temperature=85°C, Max Output Voltage=4.5V, Max Power Dissipation=1.54W, Min Operating Temperature=-40°C, Min Output Voltage=4.168V, Min Supply Voltage=3.75V, Output Current=10mA, Output Voltage=4.2V, Package Quantity=3000
U3: library part CMP-00004-1, "300mA Low-Dropout (LDO) Regulator 5-SOT-23 -40 to 125", Case/Package=SOT-23-5, Dropout Voltage=270mV, Max Input Voltage=5.5V, Max Operating Temperature=125°C, Min Operating Temperature=-40°C, Min Output Voltage=3.3V, Output Current=300mA, Power Supply Rejection Ratio (PSRR)=28dB, Quiescent Current=60uA
U4: library part CMP-00003-1, "Digital Isolator CMOS 4-CH 12Mbps 16-Pin SOIC T/R", Case/Package=SOIC, Isolated Power=No, Max Operating Temperature=105°C, Max Supply Voltage=5.5V, Min Operating Temperature=-40°C, Min Supply Voltage=3.1V, Nominal Supply Current=6mA, Package Quantity=1000
U5: library part CMP-00005-1, "IC REG LIN POS ADJ 1.1A SOT223-3", Case/Package=SOT-223, Dropout Voltage=1.35V, Max Input Voltage=36V, Max Operating Temperature=125°C, Min Current Limit=1.1A, Min Input Voltage=1.2V, Min Operating Temperature=-40°C, Operating Supply Current=300uA, Output Voltage Accuracy=1%, Package Quantity=1, Quiescent Current=500uA

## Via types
v1: diameter 1.5, hole 1, Top Layer to Bottom Layer, 112 vias
v2: diameter 0.5, hole 0.4, Top Layer to Bottom Layer, 12 vias
v3: diameter 0.5, hole 0.4, Top Layer to Bottom Layer, tented top, 6 vias
v4: diameter 0.5, hole 0.4, Top Layer to Bottom Layer, tented both sides, 6 vias
v5: diameter 3.5, hole 3, Top Layer to Bottom Layer, 4 vias

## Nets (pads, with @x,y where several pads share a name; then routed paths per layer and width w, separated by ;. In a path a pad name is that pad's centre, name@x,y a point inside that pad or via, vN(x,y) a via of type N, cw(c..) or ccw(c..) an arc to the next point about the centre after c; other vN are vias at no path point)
3V3: *1_pta_I1.6 *1_pta_I2.6 *1_pta_I3.6 *2.6 C1.2 C2.2 C3.2 C4.2 C5.2 C6.2 C7.2 C8.2 C9.2 C10.2 C38.2 CN2.5 Display.22 IC2.8 U1.26 U1.37 U1.50 U1.65 U1.75 U1.88 U1.100 U3.5 | length 333.2
  Top Layer w0.254: IC2.8@14.577,78.597 15.087,78.597 15.125,78.559 15.125,72.155 20.564,66.717 *1_pta_I1.6@20.564,66 20.764,66 21.614,66.85 31.079,66.85 32.354,65.575 *2.6@32.554,65.575 33.632,65.575 35.354,63.853 35.354,58.646 ; v1(14.619,25.97) 16.367,27.718 16.367,29.894 v1(16.229,30.033) ; C4.2@15.704,41.387 15.654,41.387 14.555,42.486 v1(14.354,42.486) 14.354,46.826 15.394,47.866 15.455,47.866 C8.2@15.817,48.228 ; C8.2@15.867,48.228 C8.2@15.817,48.228 ; 17.55,48.228 C8.2@15.817,48.228 ; 17.589,48.228 18.08,47.736 U1.100@19.889,47.736 ; C9.2@19.849,50.342 19.849,49.419 19.889,49.379 U1.100@19.889,47.736 ; 20.427,60.537 20.427,60.337 20.6,60.164 *1_pta_I2.6@20.8,60.164 20.807,60.171 22.688,60.171 22.885,59.973 22.885,59.046 25.822,56.11 34.082,56.11 35.354,57.382 35.354,58.646 ; v1(22.346,25.995) 22.128,26.213 21.215,26.213 19.689,27.739 C6.2@19.689,29.487 19.689,30.548 19.88,30.739 19.88,32.528 U1.26@19.889,32.537 19.889,33.68 20.739,34.53 24.671,34.53 24.678,34.537 24.888,34.537 25.389,34.036 U1.37@25.389,32.537 ; C10.2@24.122,50.092 C2.2@25.239,50.092 25.239,50.042 25.6,49.681 25.6,49.523 25.885,49.238 U1.88@25.885,47.737 ; C7.2@25.283,27.436 25.283,27.486 24.889,27.88 C1.2@24.889,29 24.889,30.271 25.381,30.763 U1.37@25.381,32.537 ; U1.88@25.889,47.736 25.889,44.916 ; v1(27.831,23.145) 27.881,23.195 28.695,23.195 31.095,25.595 31.095,26.296 31.995,27.196 31.995,29.251 33.305,30.562 33.305,32.537 ; v1(28.695,19.303) 28.963,19.303 30.4,17.865 C38.2@30.5,17.865 30.951,18.316 U3.5@32.55,18.316 ; U1.50@31.889,32.537 33.305,32.537 ; U1.75@33.489,46.136 31.899,46.136 30.679,44.916 ; C3.2@36.243,32.03 36.193,32.03 35.686,32.537 33.305,32.537 ; C5.2@37.176,40.117 36.256,40.117 35.236,41.136 32.058,41.136 30.679,42.516 30.679,44.916 ; v1(59.665,37.03) 38.049,58.646 35.354,58.646 ; v1(69.394,38.516) 69.521,38.643 71.952,38.643 72.125,38.816 *1_pta_I3.6@72.125,39.016 ; U1.100@19.889,47.736 19.898,47.728 19.898,46.72 21.702,44.916 25.889,44.916 ; 25.889,44.916 30.679,44.916
  Bottom Layer w0.254: Display.22@4.5,15.41 4.5,15.851 v1(14.619,25.97) ; v1(14.354,42.486) 16.229,40.612 v1(16.229,30.033) 20.266,25.995 v1(22.346,25.995) 23.464,27.114 27.168,27.114 27.831,26.451 v1(27.831,23.145) ; CN2.5@68.54,1.665 58.386,11.819 57.027,11.819 53.731,15.115 43.478,15.115 43.409,15.047 33.121,15.047 28.865,19.303 v1(28.695,19.303) 28.695,19.64 27.831,20.504 v1(27.831,23.145) ; v1(69.394,38.516) 67.908,37.03 46.066,37.03 32.181,23.145 v1(27.831,23.145)
BOOSTER_VCC: C36.1 D2.2 D3.2 IC1.23 | length 65.1
  Top Layer w0.254: v1(55.345,50.3) 55.345,50.252 57.324,48.273 57.65,48.273 v1@57.935,47.988 ; v1(55.678,59.153) 55.703,59.153 56.49,59.94 60.784,59.94 62.855,57.869 64.372,57.869 67.05,55.191 IC1.23@67.05,53.9 ; v1(57.56,47.988) 57.648,47.9 57.935,47.9 58.835,47 59.917,47 ; C36.1@59.917,46.15 59.917,47 ; D2.2@60.048,48.15 59.917,48.02 59.917,47 ; D3.2@75.841,48.15 76.266,48.15 77.416,47 v1(78.55,47)
  Bottom Layer w0.254: v1(55.345,50.3) 55.511,50.467 55.511,58.986 v1(55.678,59.153) ; v1(57.56,47.988) 57.56,45.795 62.026,41.33 62.026,40.723 62.05,40.699 62.05,40.25 62.885,39.415 64.953,39.415 72.538,47 v1(78.55,47)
